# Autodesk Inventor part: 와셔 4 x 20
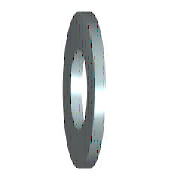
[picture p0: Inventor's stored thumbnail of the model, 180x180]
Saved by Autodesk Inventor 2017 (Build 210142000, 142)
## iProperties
IsCustomPart: 1
Created: 2012-02
Part Number: 와셔 4 x 20
Material: 강철, 연강
Description: 미터법 평면 와셔
Document SubType Name: Modeling
Standard: ANSI B18.22M
Designer: mduedu
Standard Revision: 1999
Standards Organization: ANSI
Language: ko-KR
Size Designation: 4 W
Categories: <MemberInstance><Categories><Category DisplayName="조임쇠" InternalName="e4da775c-781d-43d5-af7c-5136215cf5a6" Mnemonic="FSTN"><Category DisplayName="와셔" InternalN
Density: 1 g/cm^3
Appearance: 파란색 - 벽 페인트 - 광택
Author: mduedu
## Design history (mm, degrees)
sketch "스케치"
  geometry: C1 r 10 at (0, 0); C2 r 2.35 at (0, 0); 1 further point
  constraints: 2 centre point, 2 coincident
  dimensions: "d0" = 4.7 diameter of C2 (= SD1); "d1" = 20 diameter of C1 (= SD2)
extrude "본체" new body sketch "스케치" distance "d2" = 2.3 (= SD); taper "d3" = 0 deg
workaxis "Work Axis1"
workplane "Work Plane1"
body "Solid1"
other parameters: "SD1" = 4.7 [user parameter; used in 1 equation term], "SD2" = 20 [user parameter; used in 1 equation term], "SD" = 2.3 [user parameter; used in 1 equation term], "d4" = 0, "d5" = 0, "d6" = 0, "d7" = 0, "NND" = 4 [user parameter]
